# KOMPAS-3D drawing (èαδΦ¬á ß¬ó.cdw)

Referenced files: Чертеж крышки.cdw
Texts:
  Крышка сквозная
  Noncommercial version
  1. Литейные уклоны- 3 , литейные радиусы- 3...5мм.
  Symbol type B
  2. Неуказанные предельные откланения размеров: h14, H14,  IT14 2 .
  Ra 3,2
  Ra 6,3
  Сталь 45 ГОСТ 1050-88
  ТФ ДГТУ
Dimensions and other numbers on the sheet: 0,75; 1; 3; 66; 6; 4; 10; 2; 100; 52; 150; 0.020; 0,060; 124; 12; 6 отв.; 1:1; 9; 0,82; 0; 5; 7; 8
